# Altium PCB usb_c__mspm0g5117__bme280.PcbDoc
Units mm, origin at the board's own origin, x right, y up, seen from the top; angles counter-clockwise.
Board outline 82 x 52 mm, 2 copper layers (Top, Bottom), stack 0 mm thick; 27 components, 19 nets, 159 pads, 78 vias.
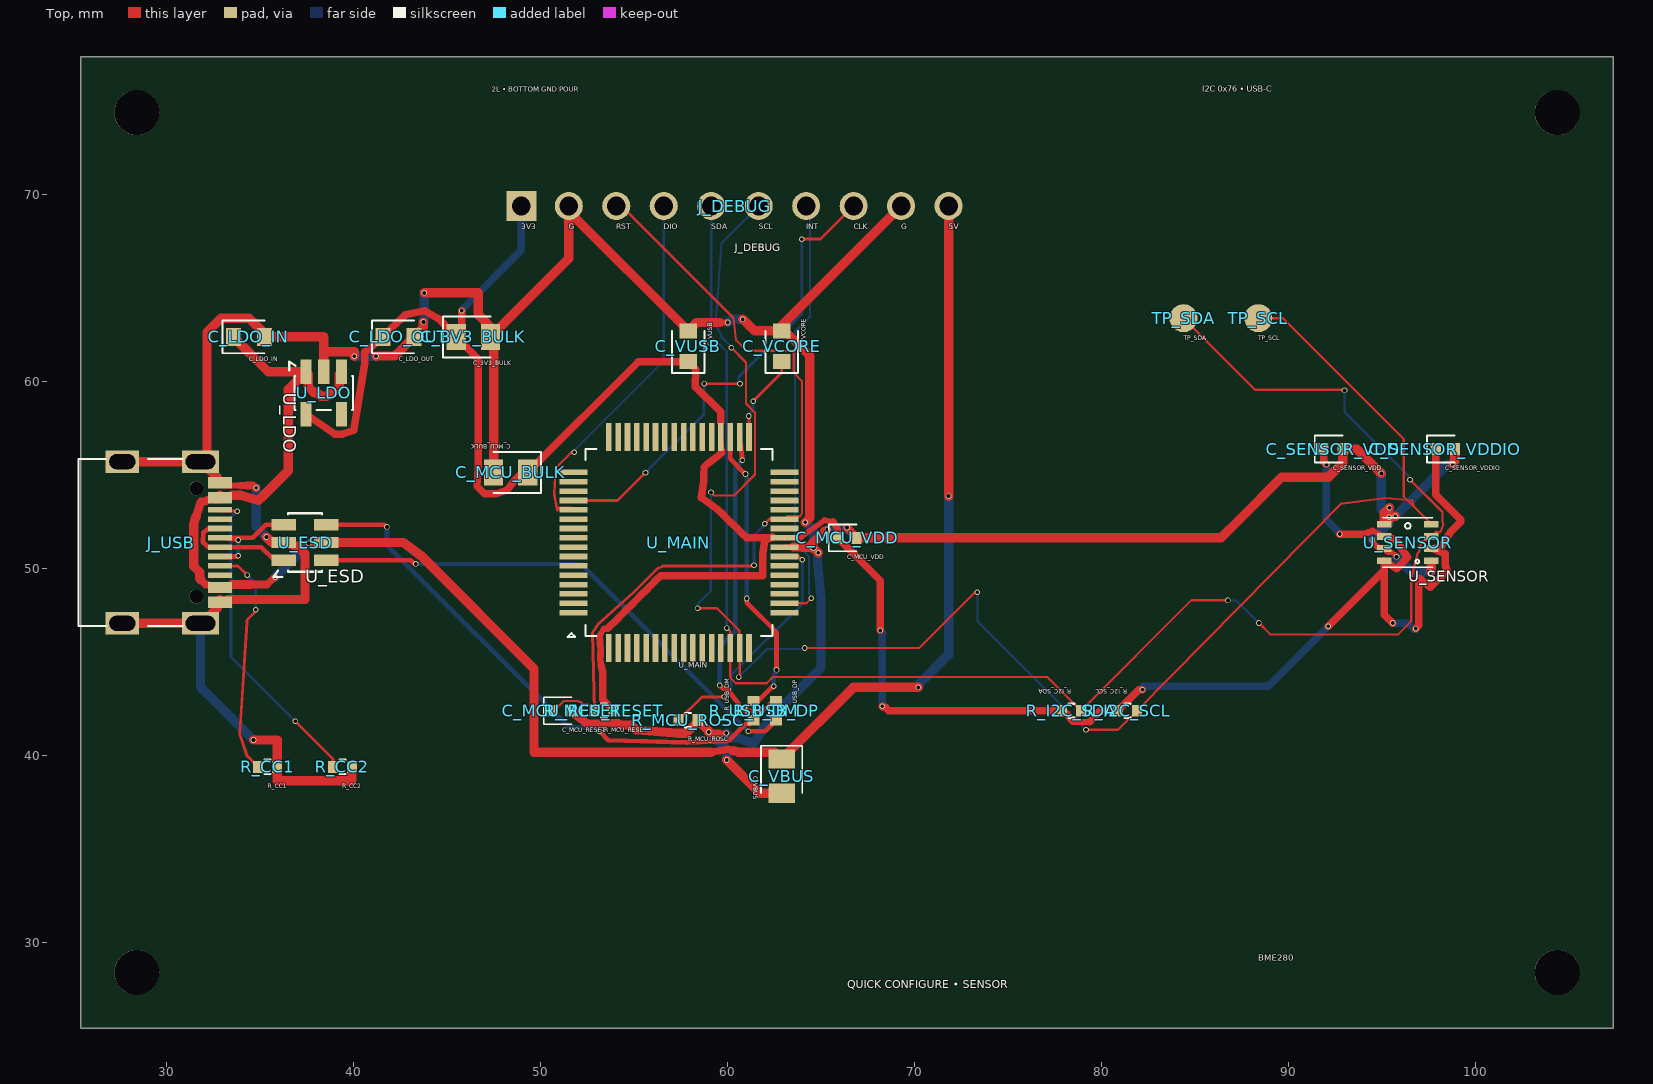
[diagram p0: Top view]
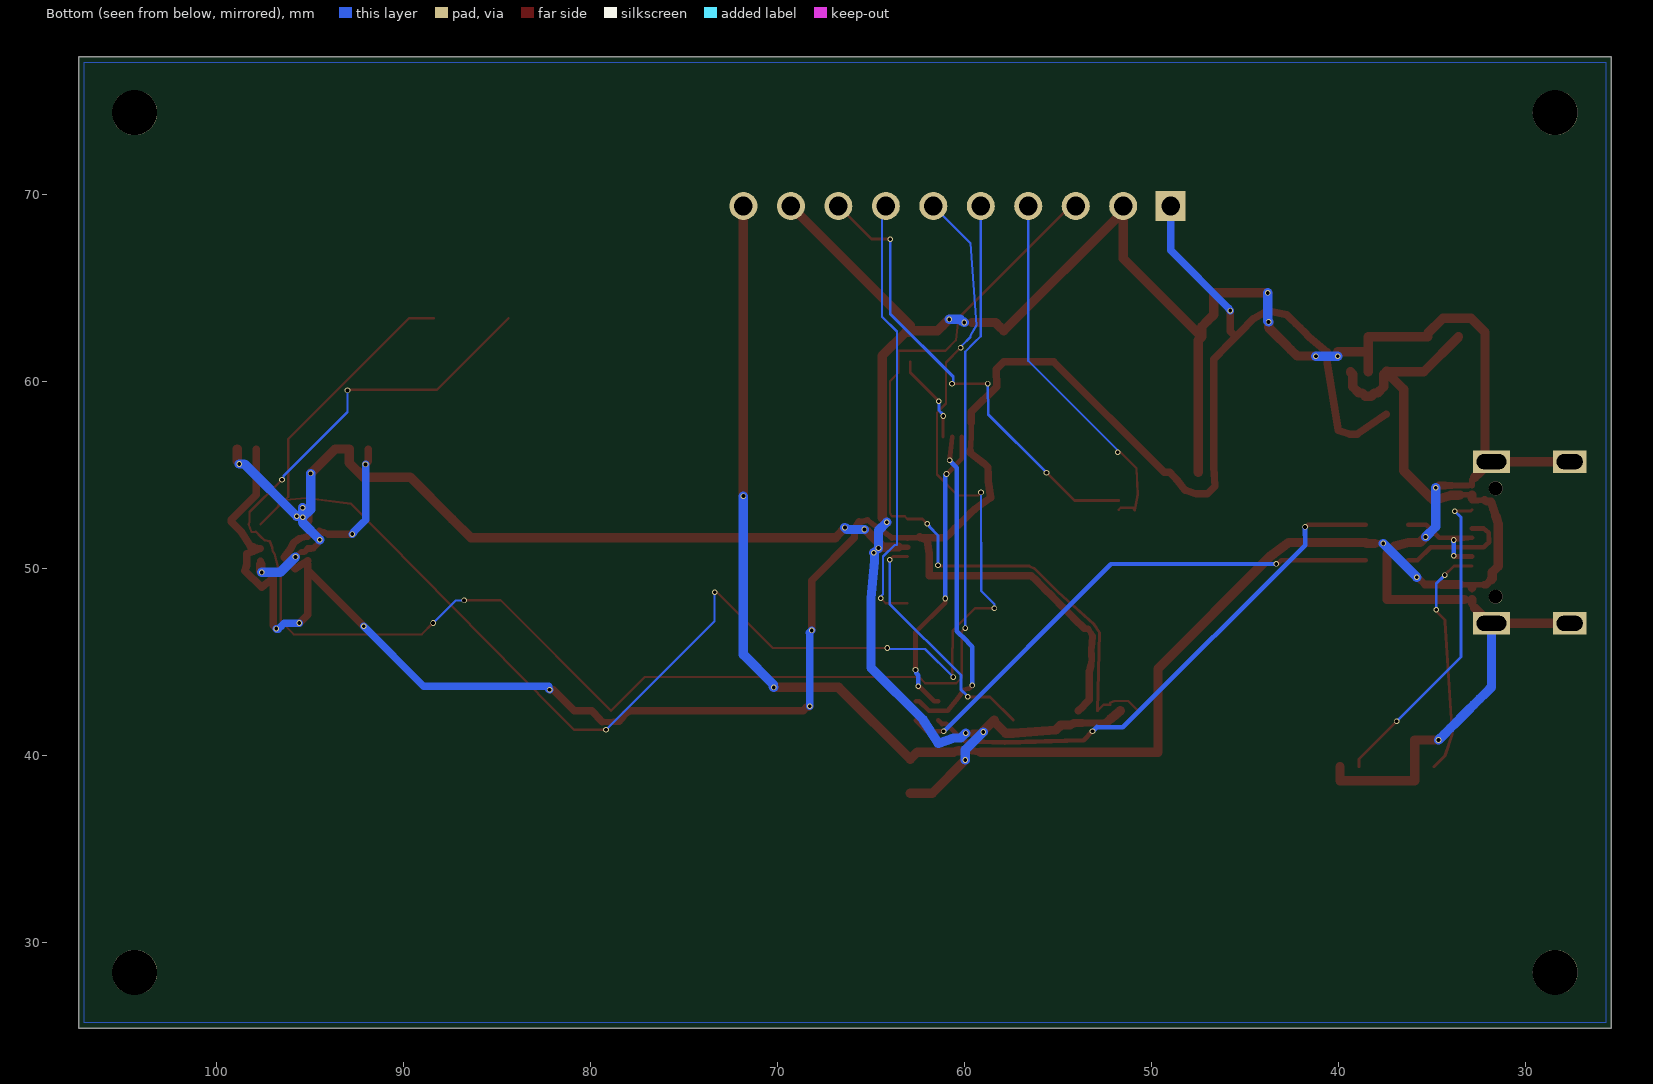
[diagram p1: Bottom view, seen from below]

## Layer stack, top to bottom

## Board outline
25.4,77.4 107.4,77.4 107.4,25.4 25.4,25.4

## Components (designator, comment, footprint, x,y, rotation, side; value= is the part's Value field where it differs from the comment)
C_3V3_BULK "" TSCIRCUIT-2.8500x1.4000mm 46.4,62.4 r0 top
C_LDO_IN "" TSCIRCUIT-2.4500x0.9500mm 34.4,62.4 r0 top
C_LDO_OUT "" TSCIRCUIT-2.4500x0.9500mm 42.4,62.4 r0 top
C_MCU_BULK "" TSCIRCUIT-2.8500x1.4000mm 48.4,55.15 r180 top
C_MCU_RESET "" TSCIRCUIT-1.5600x0.6400mm 51.15,42.4 r0 top
C_MCU_VDD "" TSCIRCUIT-1.5600x0.6400mm 66.4,51.65 r0 top
C_SENSOR_VDD "" TSCIRCUIT-1.5600x0.6400mm 92.4,56.4 r0 top
C_SENSOR_VDDIO "" TSCIRCUIT-1.5600x0.6400mm 98.4,56.4 r0 top
C_VBUS "" TSCIRCUIT-1.4000x2.8500mm 62.9,38.9 r270 top
C_VCORE "" TSCIRCUIT-0.9500x2.4500mm 62.9,61.9 r90 top
C_VUSB "" TSCIRCUIT-0.9500x2.4500mm 57.9,61.9 r90 top
J_DEBUG "" TSCIRCUIT-24.3600x1.5000mm 60.4,69.4 r0 top
J_USB "" TSCIRCUIT-6.7732x9.8502mm 30.113,51.4 r90 top
R_CC1 "" TSCIRCUIT-1.5600x0.6400mm 35.4,39.4 r0 top
R_CC2 "" TSCIRCUIT-1.5600x0.6400mm 39.4,39.4 r0 top
R_I2C_SCL "" TSCIRCUIT-1.5600x0.6400mm 81.4,42.4 r180 top
R_I2C_SDA "" TSCIRCUIT-1.5600x0.6400mm 78.4,42.4 r180 top
R_MCU_RESET "" TSCIRCUIT-1.5600x0.6400mm 53.4,42.4 r0 top
R_MCU_ROSC "" TSCIRCUIT-1.5600x0.6400mm 57.9,41.9 r0 top
R_USB_DM "" TSCIRCUIT-0.6400x1.5600mm 61.4,42.4 r90 top
R_USB_DP "" TSCIRCUIT-0.6400x1.5600mm 62.6,42.4 r90 top
TP_SCL "" TSCIRCUIT-1.5000x1.5000mm 88.4,63.4 r0 top
TP_SDA "" TSCIRCUIT-1.5000x1.5000mm 84.4,63.4 r0 top
U_ESD "" TSCIRCUIT-3.6000x2.5000mm 37.4,51.4 r0 top
U_LDO "" TSCIRCUIT-2.5000x3.6000mm 38.4,59.4 r270 top
U_MAIN "" TSCIRCUIT-12.8000x12.8000mm 57.4,51.4 r0 top
U_SENSOR "" TSCIRCUIT-3.2841x2.3142mm 96.4,51.4 r0 top

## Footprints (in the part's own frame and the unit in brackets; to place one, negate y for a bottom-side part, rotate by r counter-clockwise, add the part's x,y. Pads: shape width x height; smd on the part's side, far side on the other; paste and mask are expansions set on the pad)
TSCIRCUIT-0.6400x1.5600mm [mm]
  rect 0.54x0.64 smd: 1(-0.51,0) 2(0.51,0)
  silkscreen extent -0.15,-0.38 0.15,0.38
TSCIRCUIT-0.9500x2.4500mm [mm]
  rect 0.8x0.95 smd: 1(-0.825,0) 2(0.825,0)
  silkscreen extent -1.43,-0.87 0.82,0.88
TSCIRCUIT-1.4000x2.8500mm [mm]
  rect 1.025x1.4 smd: 1(-0.913,0) 2(0.913,0)
  silkscreen extent -1.62,-1.1 0.91,1.1
TSCIRCUIT-1.5000x1.5000mm [mm]
  round 1.5 smd: 1(0,0)
TSCIRCUIT-1.5600x0.6400mm [mm]
  rect 0.54x0.64 smd: 1(-0.51,0) 2(0.51,0)
  silkscreen extent -0.98,-0.72 0.51,0.72
TSCIRCUIT-2.4500x0.9500mm [mm]
  rect 0.8x0.95 smd: 1(-0.825,0) 2(0.825,0)
  silkscreen extent -1.43,-0.87 0.82,0.87
TSCIRCUIT-2.5000x3.6000mm [mm]
  rect 1.325x0.6 smd: 1(-1.137,-0.95) 2(-1.137,0) 3(-1.137,0.95) 4(1.138,0.95) 5(1.138,-0.95)
  silkscreen extent -1.69,-1.84 0.91,1.56
TSCIRCUIT-2.8500x1.4000mm [mm]
  rect 1.025x1.4 smd: 1(-0.913,0) 2(0.913,0)
  silkscreen extent -1.63,-1.1 0.91,1.1
TSCIRCUIT-3.2841x2.3142mm [mm]
  rect 0.767x0.364 smd: 1(1.259,-0.975) 2(1.259,-0.325) 3(1.259,0.325) 4(1.259,0.975) 5(-1.259,0.975) 6(-1.259,0.325) 7(-1.259,-0.325) 8(-1.259,-0.975)
  silkscreen extent -1.33,-1.33 1.33,1.33
TSCIRCUIT-3.6000x2.5000mm [mm]
  rect 1.325x0.6 smd: 1(-1.137,-0.95) 2(-1.137,0) 3(-1.137,0.95) 4(1.138,0.95) 5(1.138,0) 6(1.138,-0.95)
  silkscreen extent -1.69,-1.84 0.91,1.56
TSCIRCUIT-6.7732x9.8502mm [mm]
  rect 0.3x1.3 smd: 1(-3.35,-2.737) 2(-3.05,-2.737) 3(-2.55,-2.737) 4(-2.25,-2.737) 5(-1.75,-2.737) 6(-1.25,-2.737) 7(-0.75,-2.737) 8(-0.25,-2.737) 9(0.25,-2.737) 10(0.75,-2.737) 11(1.25,-2.737) 12(1.75,-2.737) 13(2.55,-2.737) 14(2.25,-2.737) 15(3.35,-2.737) 16(3.05,-2.737)
  rect 1.2x2 hole 0.8 slot 1.6 at 90 deg: 17(-4.325,-1.693) 18(4.325,-1.693)
  rect 1.2x1.8 hole 0.8 slot 1.4 at 90 deg: 19(4.325,2.487) 20(-4.325,2.487)
  round 0.75 hole 0.75 unplated: NPTH-1(-2.9,-1.468) NPTH-2(2.9,-1.468)
  silkscreen extent -4.47,-0.75 4.47,4.83
TSCIRCUIT-12.8000x12.8000mm [mm]
  rect 1.5x0.3 smd: 1(-5.65,-3.75) 2(-5.65,-3.25) 3(-5.65,-2.75) 4(-5.65,-2.25) 5(-5.65,-1.75) 6(-5.65,-1.25) 7(-5.65,-0.75) 8(-5.65,-0.25) 9(-5.65,0.25) 10(-5.65,0.75) 11(-5.65,1.25) 12(-5.65,1.75) 13(-5.65,2.25) 14(-5.65,2.75) 15(-5.65,3.25) 16(-5.65,3.75) 33(5.65,3.75) 34(5.65,3.25) 35(5.65,2.75) 36(5.65,2.25) 37(5.65,1.75) 38(5.65,1.25) 39(5.65,0.75) 40(5.65,0.25) 41(5.65,-0.25) 42(5.65,-0.75) 43(5.65,-1.25) 44(5.65,-1.75) 45(5.65,-2.25) 46(5.65,-2.75) 47(5.65,-3.25) 48(5.65,-3.75)
  rect 0.3x1.5 smd: 17(-3.75,5.65) 18(-3.25,5.65) 19(-2.75,5.65) 20(-2.25,5.65) 21(-1.75,5.65) 22(-1.25,5.65) 23(-0.75,5.65) 24(-0.25,5.65) 25(0.25,5.65) 26(0.75,5.65) 27(1.25,5.65) 28(1.75,5.65) 29(2.25,5.65) 30(2.75,5.65) 31(3.25,5.65) 32(3.75,5.65) 49(3.75,-5.65) 50(3.25,-5.65) 51(2.75,-5.65) 52(2.25,-5.65) 53(1.75,-5.65) 54(1.25,-5.65) 55(0.75,-5.65) 56(0.25,-5.65) 57(-0.25,-5.65) 58(-0.75,-5.65) 59(-1.25,-5.65) 60(-1.75,-5.65) 61(-2.25,-5.65) 62(-2.75,-5.65) 63(-3.25,-5.65) 64(-3.75,-5.65)
  silkscreen extent -5.95,-5.05 5,5
TSCIRCUIT-24.3600x1.5000mm [mm]
  rect 1.6x1.6 hole 1: 1(-11.43,0)
  round 1.5 hole 1: 2(-8.89,0) 3(-6.35,0) 4(-3.81,0) 5(-1.27,0) 6(1.27,0) 7(3.81,0) 8(6.35,0) 9(8.89,0) 10(11.43,0)

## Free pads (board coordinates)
  round 2.4 hole 2.4 unplated: NPTH-3(28.4,28.4) NPTH-4(104.4,28.4) NPTH-5(28.4,74.4) NPTH-6(104.4,74.4)

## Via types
v1: diameter 0.3, hole 0.2, Top to Bottom, 78 vias

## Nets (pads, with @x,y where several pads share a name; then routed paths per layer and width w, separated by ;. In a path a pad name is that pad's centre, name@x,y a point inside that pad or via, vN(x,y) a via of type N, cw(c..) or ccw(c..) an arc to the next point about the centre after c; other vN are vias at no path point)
".J_DEBUG > .pin4 to .U_MAIN > .pin12": J_DEBUG.4 U_MAIN.12 | length 19.8
  Top w0.12: U_MAIN.12 51.641,53.259 50.973,53.259 50.895,53.127 50.728,53.972 50.797,55.377 50.874,55.454 51.654,56.234 v1(51.8,56.234)
  Bottom w0.12: v1(51.8,56.234) 51.836,56.27 51.836,56.369 56.59,61.124 J_DEBUG.4
".J_DEBUG > .pin8 to .U_MAIN > .pin13": J_DEBUG.8 U_MAIN.13 | length 25.1
  Top w0.15: U_MAIN.13 54.123,53.65 v1(55.612,55.139) ; v1(58.759,59.903) 58.754,59.898 58.918,59.898 v1(60.667,59.898) ; v1(63.971,67.619) 63.983,67.631 64.981,67.631 J_DEBUG.8
  Bottom w0.15: v1(55.612,55.139) 55.64,55.167 58.735,58.262 v1(58.759,59.903) ; v1(60.667,59.898) 60.604,59.961 60.604,60.265 63.971,63.632 v1(63.971,67.619)
".U_MAIN > .pin42 to .R_MCU_ROSC > .pin1": R_MCU_ROSC.1 U_MAIN.42 | length 13
  Top w0.15: R_MCU_ROSC.1 58.63,43.14 v1(59.82,43.142) ; U_MAIN.42 63.825,50.65 63.984,50.491 v1(64.004,50.471)
  Bottom w0.15: v1(59.82,43.142) 59.844,43.166 59.844,43.182 60.188,43.526 60.188,44.303 64.004,48.119 v1(64.004,50.471)
GND: C_3V3_BULK.2 C_LDO_IN.2 C_LDO_OUT.2 C_MCU_BULK.2 C_MCU_RESET.2 C_MCU_VDD.2 C_SENSOR_VDD.2 C_SENSOR_VDDIO.2 C_VBUS.2 C_VCORE.2 C_VUSB.2 J_DEBUG.2 J_DEBUG.9 J_USB.1 J_USB.2 J_USB.15 J_USB.16 J_USB.17 J_USB.18 J_USB.19 J_USB.20 R_CC1.2 R_CC2.2 R_MCU_ROSC.2 U_ESD.2 U_LDO.2 U_MAIN.41 U_SENSOR.1 U_SENSOR.5 U_SENSOR.7 | length 209.8
  Top w0.25: U_SENSOR.7@95.462,50.9 95.713,50.775 v1(95.789,50.628)
  Top w0.275: J_USB.2 J_USB.2@33.271,48.35
  Top w0.3: J_USB.1@32.699,47.9 J_USB.1 J_USB.2@32.849,48.2 ; 32.699,54.9 J_USB.15 J_USB.16@32.849,54.6 ; J_USB.16 32.945,54.461 33.037,54.45 J_USB.16@33.318,54.45 ; U_MAIN.41@63.526,51.15 U_MAIN.41 ; U_MAIN.41@63.55,51.15 U_MAIN.41 ; U_MAIN.41@63.8,51.15 63.706,51.15 63.612,51.15 63.519,51.15 63.425,51.15 63.331,51.15 63.238,51.15 63.144,51.15 U_MAIN.41
  Top w0.31: J_USB.16 J_USB.15@32.849,54.6
  Top w0.312: J_USB.16@33.318,54.45 33.599,54.45 ; v1(94.491,51.553) 94.525,51.4 U_SENSOR.7@94.837,51.088
  Top w0.325: 33.599,54.45 33.941,54.45 ; 59.535,41.192 v1(59.939,41.205) ; 59.596,63.169 v1(60.013,63.169) ; U_SENSOR.7@94.837,51.088 U_SENSOR.7@94.969,51.075 ; U_SENSOR.7 95.335,50.881 U_SENSOR.7@95.462,50.9
  Top w0.35: 33.941,54.45 34.283,54.45 ; 65.199,51.996 65.237,51.996 v1(65.354,52.095)
  Top w0.364: U_SENSOR.7@94.969,51.075 U_SENSOR.7 ; U_SENSOR.5@95.141,52.557 U_SENSOR.5 ; U_SENSOR.1@97.659,50.243 U_SENSOR.1 ; U_SENSOR.5 95.323,52.557 U_SENSOR.5
  Top w0.375: 52.431,41.744 52.853,41.744 53.275,41.744
  Top w0.4: 53.275,41.744 53.697,41.744
  Top w0.425: 34.283,54.45 34.625,54.45 34.784,54.329 v1(34.786,54.327) ; 58.89,41.42 59.13,41.18 59.535,41.192
  Top w0.45: 52.174,41.962 52.431,41.744 ; 53.697,41.744 54.119,41.744 54.36,41.639 ; v1(66.4,52.2) 66.655,51.925 C_MCU_VDD.2
  Top w0.475: U_MAIN.41@63.526,51.15 64.003,51.15 ; U_MAIN.41@63.55,51.15 64.05,51.15 ; U_MAIN.41@63.8,51.15 64.076,51.15
  Top w0.5: J_USB.20 J_USB.17 31.874,47.075 32.474,47.675 J_USB.1@32.699,47.9 ; J_USB.19 J_USB.18 ; 32.699,54.9 32.474,55.125 31.874,55.725 J_USB.18 ; J_USB.1@32.849,48.2 J_USB.2 ; J_USB.2@33.271,48.35 33.693,48.35 37.4,48.35 37.4,50.8 37,51.2 U_ESD.2 35.63,51.4 v1(35.333,51.697) ; v1(34.641,40.833) 35.91,40.833 R_CC1.2 35.91,38.65 39.91,38.65 R_CC2.2 ; v1(40.032,61.365) 40.032,61.6 38.4,61.6 U_LDO.2 38.4,62.4 C_LDO_IN.2 35.225,62.575 34.4,63.4 32.9,63.4 32.154,62.654 32.154,56.073 J_USB.18 ; v1(41.2,61.367) 41.209,61.376 41.399,61.376 41.8,61.376 42.201,61.376 42.542,61.717 42.884,62.059 C_LDO_OUT.2 43.732,62.907 v1(43.732,63.2) ; v1(43.779,64.753) 46.657,64.753 46.657,63.598 46.985,63.271 47.313,62.943 47.313,62.671 C_3V3_BULK.2 ; C_MCU_BULK.2 47.487,62.225 C_3V3_BULK.2 ; C_MCU_RESET.2 51.917,42.181 52.174,41.962 ; 54.36,41.639 54.845,41.639 55.113,41.37 57.4,41.2 57.8,41.2 58.41,41.81 R_MCU_ROSC.2 ; 58.89,41.42 58.65,41.66 R_MCU_ROSC.2 ; v1(59,41.261) 59,41.31 R_MCU_ROSC.2 ; 59.596,63.169 59.178,63.169 58.761,63.169 58.344,63.169 58.122,62.947 C_VUSB.2 51.51,69.115 J_DEBUG.2 51.51,66.597 C_3V3_BULK.2 ; v1(59.956,39.762) 61.731,37.988 C_VBUS.2 ; v1(60.816,63.335) 60.867,63.284 60.882,63.284 61.162,63.005 61.441,62.725 61.927,62.725 62.414,62.725 C_VCORE.2 ; 64.003,51.15 64.479,51.15 64.529,51.1 v1(64.6,51.1) ; 64.05,51.15 v1@64.549,51.15 ; 64.076,51.15 64.353,51.15 64.635,51.432 64.917,51.714 65.199,51.996 ; v1(64.162,52.485) 64.4,52.723 64.4,60.9 64.4,61.4 63.15,62.65 62.975,62.65 C_VCORE.2 ; v1@64.55,51.15 v1(64.85,50.85) ; C_MCU_VDD.2 67.404,51.65 67.899,51.65 68.393,51.65 68.887,51.65 69.382,51.65 69.876,51.65 70.37,51.65 70.865,51.65 71.359,51.65 71.853,51.65 72.348,51.65 72.842,51.65 73.336,51.65 73.831,51.65 74.325,51.65 74.819,51.65 75.314,51.65 75.808,51.65 76.302,51.65 76.797,51.65 77.291,51.65 77.785,51.65 78.28,51.65 86.4,51.65 87.4,52.65 89.65,54.9 92.15,54.9 92.91,55.66 C_SENSOR_VDD.2 93.666,56.4 94.899,55.167 94.912,55.167 v1(94.983,55.096) ; J_DEBUG.9 62.9,63.01 C_VCORE.2 ; 95.141,52.557 95.141,52.992 v1(95.414,53.265) ; v1(95.4,52.75) 95.4,52.634 95.323,52.557 95.566,52.8 v1(95.725,52.8) ; v1(97.6,49.8) 97.659,49.859 U_SENSOR.1@97.659,50.243 ; v1(98.8,55.6) 98.834,55.634 98.834,55.681 98.91,55.757 C_SENSOR_VDDIO.2
  Bottom w0.5: J_USB.17 31.806,46.588 31.806,46.1 31.806,45.613 31.806,45.126 31.806,44.639 31.806,44.151 31.806,43.664 32.121,43.349 32.436,43.035 32.751,42.72 33.066,42.406 33.381,42.091 33.696,41.777 34.011,41.462 34.326,41.148 v1(34.641,40.833) ; v1(34.786,54.327) 34.786,52.244 v1(35.333,51.697) ; v1(40.032,61.365) 40.038,61.359 40.204,61.359 40.213,61.367 40.706,61.367 v1(41.2,61.367) ; v1(43.732,63.2) 43.779,63.247 v1(43.779,64.753) ; v1(59,41.261) 59.956,40.305 v1(59.956,39.762) ; v1(59.939,41.205) 60.205,40.938 60.568,40.938 61.4,40.65 62.214,41.914 65,44.701 65,48.4 64.816,50.391 64.816,50.884 v1(64.85,50.85) ; v1(60.013,63.169) 60.066,63.222 60.114,63.222 60.227,63.335 60.522,63.335 v1(60.816,63.335) ; v1(64.162,52.485) 64.6,52.047 v1(64.6,51.1) ; v1(65.354,52.095) 66.295,52.095 v1(66.4,52.2) ; v1(94.491,51.553) 95.414,52.476 v1(95.414,53.265) ; v1(94.983,55.096) 94.983,53.167 v1(95.4,52.75) ; v1(95.725,52.8) 98.525,55.6 v1(98.8,55.6) ; v1(95.789,50.628) 96.617,49.8 v1(97.6,49.8)
MAIN_RESET: C_MCU_RESET.1 J_DEBUG.3 R_MCU_RESET.1 U_MAIN.38 | length 43.8
  Top w0.12: C_MCU_RESET.1 50.822,42.506 51.222,42.906 51.598,42.915 51.998,42.906 52.213,42.826 52.209,42.722 52.568,42.722 R_MCU_RESET.1 ; J_DEBUG.3 54.332,69.4 60.32,63.412 60.462,62.221 61.019,61.664 63.468,61.664 63.55,61.664 63.55,60.481 63.984,60.032 63.984,53.433 63.984,53.326 63.989,53.003 63.93,52.85 63.866,52.799 63.199,52.799 U_MAIN.38
  Top w0.15: R_MCU_RESET.1 52.777,46.592 53.087,47.042 54.995,48.753 56.04,49.795 56.251,50.002 56.53,50.139 61.28,50.139 61.374,50.139 v1(61.418,50.183) ; v1(62,52.4) 62.25,52.65 U_MAIN.38
  Bottom w0.15: v1(61.418,50.183) 61.418,51.778 61.88,52.24 61.88,52.28 v1(62,52.4)
MSP_VCORE: C_VCORE.1 U_MAIN.32 | length 4.8
  Top w0.15: v1(61.143,58.169) 61.143,57.057 U_MAIN.32 ; v1(61.373,58.961) 61.407,58.995 62.9,60.488 C_VCORE.1
  Bottom w0.15: v1(61.143,58.169) 61.19,58.216 61.19,58.288 61.373,58.471 v1(61.373,58.961)
SENSOR_INT: J_DEBUG.7 U_MAIN.47 | length 23.4
  Top w0.12: U_MAIN.47 64.215,48.15 v1(64.482,48.417)
  Bottom w0.12: J_DEBUG.7 64.413,69.197 64.413,63.484 63.612,62.683 63.612,51.27 63.739,51.27 64.356,50.653 64.356,48.632 64.516,48.471 64.516,48.451 v1(64.482,48.417)
SENSOR_SCL: J_DEBUG.6 R_I2C_SCL.1 TP_SCL.1 U_MAIN.50 U_SENSOR.4 | length 94.9
  Top w0.12: v1(58.402,47.883) 59.435,47.883 60.626,46.692 60.626,45.774 U_MAIN.50 60.65,44.321 60.6,44.271 v1(60.6,44.2) ; v1(59.121,54.079) 59.136,54.024 59.161,54.024 59.277,53.908 60.35,53.908 61.476,55.035 61.476,58.347 60.992,58.831 60.992,58.894 60.992,61.036 v1(60.21,61.818) ; v1(64.133,45.754) 70.259,45.754 73.233,48.728 73.359,48.728 v1(73.369,48.738) ; v1(79.178,41.386) 80.896,41.386 R_I2C_SCL.1 92.827,53.476 95.205,53.786 96.629,53.644 96.713,53.321 U_SENSOR.4 96.185,53.849 96.185,56.937 89.721,63.4 TP_SCL.1
  Bottom w0.12: v1(58.402,47.883) 58.402,48.104 59.099,48.801 v1(59.121,54.079) ; v1(60.21,61.818) 60.147,61.881 60.147,61.921 59.676,62.392 59.676,62.476 59.357,63.03 59.676,67.406 J_DEBUG.6 ; v1(60.6,44.2) 62.108,45.708 63.974,45.708 64.087,45.708 v1(64.133,45.754) ; v1(73.369,48.738) 73.369,47.195 79.167,41.397 v1(79.178,41.386)
SENSOR_SDA: J_DEBUG.5 R_I2C_SDA.1 TP_SDA.1 U_MAIN.51 U_SENSOR.3 | length 92.1
  Top w0.12: v1(59.965,46.82) 60.069,46.716 60.15,46.635 U_MAIN.51 60.15,44.17 60.447,43.873 62.096,43.873 62.43,44.207 77.103,44.207 R_I2C_SDA.1 84.818,48.308 86.713,48.308 86.767,48.308 v1(86.773,48.302) ; TP_SDA.1 88.227,59.573 92.815,59.573 92.971,59.573 v1(93.008,59.536) ; v1(88.432,47.091) 89.038,46.485 95.886,46.485 96.582,47.182 96.582,49.511 96.916,50.809 97.026,50.964 97.039,51.125 97.167,51.467 97.419,51.522 97.455,51.522 U_SENSOR.3 97.907,51.974 97.912,51.979 98.143,51.958 98.299,52.389 98.248,52.487 98.248,53.028 v1(96.514,54.762)
  Bottom w0.12: J_DEBUG.5 59.13,62.439 59.46,62.11 59.965,61.604 v1(59.965,46.82) ; v1(86.773,48.302) 87.212,48.302 88.315,47.199 88.324,47.199 v1(88.432,47.091) ; v1(93.008,59.536) 93.008,58.376 96.43,54.954 96.43,54.846 v1(96.514,54.762)
usb-dm-mcu: R_USB_DM.2 U_MAIN.30 | length 15.8
  Top w0.25: U_MAIN.30 60.15,55.874 v1(60.961,55.063) ; v1(61.024,48.403) 61.039,48.388 61.039,48.176 62.622,46.594 v1(62.622,44.584) ; R_USB_DM.2 61.62,42.91 62.348,43.639 62.418,43.639 v1(62.482,43.703)
  Bottom w0.25: v1(60.961,55.063) 61.024,55 61.024,54.902 v1(61.024,48.403) ; v1(62.482,43.703) 62.482,44.304 62.587,44.409 62.587,44.549 v1(62.622,44.584)
usb-dm-phy: R_USB_DM.1 U_ESD.4 | length 28.7
  Top w0.25: U_ESD.4 41.622,52.35 41.739,52.233 v1(41.78,52.233) ; v1(53.154,41.301) 53.619,40.827 57.843,40.701 59.956,40.761 60.125,40.837 60.974,41.705 61.204,41.694 R_USB_DM.1
  Bottom w0.25: v1(41.78,52.233) 41.764,51.265 51.533,41.523 52.93,41.525 53.149,41.306 v1(53.154,41.301)
usb-dm-port: J_USB.7 J_USB.9 U_ESD.3 | length 6.5
  Top w0.25: J_USB.7 33.099,50.65 33.349,50.65 33.599,50.65 33.784,50.65 v1(33.823,50.689) ; v1(33.827,51.533) J_USB.9 34.609,51.65 35.309,52.35 U_ESD.3
  Bottom w0.25: v1(33.823,50.689) 33.823,50.929 33.823,51.169 33.823,51.41 33.843,51.43 33.843,51.483 v1(33.827,51.533)
usb-dp-mcu: R_USB_DP.2 U_MAIN.31 | length 17.7
  Top w0.25: v1(59.58,43.753) 59.67,43.663 59.759,43.574 59.859,43.574 60.025,43.525 60.349,43.084 60.9,42.4 61.9,42.4 62.42,42.91 R_USB_DP.2 ; U_MAIN.31 v1(60.8,55.8)
  Bottom w0.25: v1(59.58,43.753) 59.58,43.984 59.58,44.214 59.58,44.445 59.58,44.675 59.58,44.906 59.58,45.136 59.58,45.367 59.58,45.597 59.58,45.828 59.746,45.994 59.912,46.159 60.078,46.325 60.243,46.491 60.409,46.657 60.409,46.907 60.409,47.156 60.409,47.406 60.409,47.656 60.409,47.906 60.409,48.155 60.409,48.405 60.409,48.655 60.409,48.905 60.409,49.154 60.409,49.404 60.409,49.654 60.409,49.904 60.409,50.153 60.409,50.403 60.409,50.653 60.409,50.902 60.409,51.152 60.409,51.402 60.409,51.652 60.409,51.901 60.409,52.151 60.409,52.401 60.409,52.651 60.409,52.9 60.409,53.15 60.409,53.4 60.409,53.65 60.409,53.899 60.409,54.149 60.409,54.399 60.409,54.648 60.409,54.898 60.409,55.148 60.409,55.398 60.545,55.533 60.681,55.669 60.681,55.681 v1(60.8,55.8)
usb-dp-phy: R_USB_DP.1 U_ESD.6 | length 28.1
  Top w0.25: U_ESD.6 43.047,50.45 43.217,50.28 43.275,50.28 v1(43.328,50.255) ; v1(61.119,41.296) 62.019,41.309 R_USB_DP.1
  Bottom w0.25: v1(43.328,50.255) 52.174,50.241 61.095,41.315 v1(61.119,41.296)
usb-dp-port: J_USB.8 J_USB.10 U_ESD.1 | length 6.2
  Top w0.25: J_USB.10 32.644,52.15 32.44,52.15 32.235,52.15 31.955,51.916 31.938,51.423 32.076,51.285 32.214,51.147 32.425,51.147 32.635,51.147 32.846,51.147 J_USB.8 35.065,51.135 35.764,50.451 U_ESD.1@36.262,50.451
USB_CC1: J_USB.6 R_CC1.1 | length 12.6
  Top w0.15: J_USB.6 33.811,50.15 v1(34.305,49.656) ; v1(34.762,47.804) 34.756,47.798 34.756,47.716 34.299,47.259 34.299,47.155 33.906,41.148 34.296,39.991 R_CC1.1
  Bottom w0.15: v1(34.305,49.656) 34.336,49.625 34.762,49.199 v1(34.762,47.804)
USB_CC2: J_USB.12 R_CC2.1 | length 17
  Top w0.15: J_USB.12 32.92,53.079 v1(33.779,53.079) ; v1(36.883,41.831) 36.892,41.822 38.89,39.824 R_CC2.1
  Bottom w0.15: v1(33.779,53.079) 33.757,53.057 33.753,53.057 33.445,52.749 33.445,52.689 33.445,45.269 v1(36.883,41.831)
VBUS5: C_LDO_IN.1 C_VBUS.1 J_DEBUG.10 J_USB.3 J_USB.4 J_USB.13 J_USB.14 U_ESD.5 U_LDO.1 U_LDO.3 | length 99.4
  Top w0.275: J_USB.3 J_USB.4@32.849,49
  Top w0.3: 32.181,53.666 32.536,53.65 J_USB.14 32.849,53.8 ; J_USB.4@32.199,49.15 J_USB.4 ; J_USB.3@32.849,49 J_USB.4 ; J_USB.13 32.943,53.95 33.037,53.95 33.13,53.95 33.224,53.95 33.318,53.95 33.412,53.95 33.499,53.95 ; 33.499,49.15 33.412,49.15 33.318,49.15 33.224,49.15 33.13,49.15 33.037,49.15 32.943,49.15 J_USB.4
  Top w0.35: v1(37.6,51.35) U_ESD.5@38.044,51.35
  Top w0.375: 35.37,49.15 35.709,49.489 35.75,49.489 v1(35.8,49.539)
  Top w0.4: 31.838,49.4 32.087,49.15 J_USB.4@32.199,49.15 ; 59.134,40.187 59.58,40.262 60.025,40.338 60.307,40.262
  Top w0.425: 34.485,49.15 34.927,49.15 35.37,49.15
  Top w0.437: 31.706,53.194 31.838,53.588 32.056,53.588 32.181,53.666
  Top w0.45: 31.575,52.8 31.706,53.194
  Top w0.475: J_USB.13@32.849,53.8 J_USB.13 ; 33.499,49.15 33.505,49.15 33.599,49.15 ; 33.499,53.95 33.505,53.95 33.599,53.932
  Top w0.5: 31.575,52.8 31.444,52.406 31.444,50.125 31.761,49.807 31.761,49.476 31.838,49.4 ; C_LDO_IN.1 35.438,60.537 U_LDO.1 ; 33.599,49.15 34.042,49.15 34.485,49.15 ; 33.599,53.932 33.988,53.922 34.9,53.65 35.155,53.893 36.51,55.248 36.51,59.597 U_LDO.1 ; U_ESD.5@38.044,51.35 38.487,51.35 U_ESD.5 38.993,51.4 39.449,51.401 39.905,51.401 40.361,51.401 40.817,51.402 41.273,51.402 41.729,51.403 42.185,51.403 42.641,51.403 43.65,50.65 49.65,44.65 49.65,43.65 49.65,40.185 55.738,40.185 56.223,40.185 56.708,40.186 57.194,40.186 57.679,40.186 58.164,40.186 58.649,40.186 59.134,40.187 ; U_LDO.3 39.35,60.517 39.233,60.4 39.233,59.733 38.9,59.4 38.733,59.4 38.567,59.233 38.233,59.233 38.067,59.4 37.9,59.4 37.567,59.733 37.567,60.4 37.4,60.567 37.421,60.567 U_LDO.1 ; 60.307,40.262 60.59,40.187 62.525,40.187 C_VBUS.1 66.737,43.649 v1(70.2,43.649) ; v1(71.83,53.884) 71.83,53.9 J_DEBUG.10
  Bottom w0.5: v1(35.8,49.539) 35.8,49.55 v1(37.6,51.35) ; v1(70.2,43.649) 70.228,43.677 70.228,43.8 71.83,45.402 v1(71.83,53.884)
VCC_3V3: C_3V3_BULK.1 C_LDO_OUT.1 C_MCU_BULK.1 C_MCU_VDD.1 C_SENSOR_VDD.1 C_SENSOR_VDDIO.1 C_VUSB.1 J_DEBUG.1 R_I2C_SCL.2 R_I2C_SDA.2 R_MCU_RESET.2 U_LDO.5 U_MAIN.29 U_MAIN.40 U_SENSOR.2 U_SENSOR.6 U_SENSOR.8 | length 149.9
  Top w0.275: 64.404,52.03 64.669,52.22 64.935,52.41 65.2,52.6
  Top w0.3: 53.25,46.575 53.35,46.75 53.4,46.775 ; 59.65,57.8 59.65,57.75 59.65,57.65 59.65,57.55 59.65,57.45 59.65,57.35 59.65,57.25 59.65,57.15 U_MAIN.29 U_MAIN.29@59.694,56.3 ; U_MAIN.40@62.375,51.65 62.712,51.65 U_MAIN.40 ; 94.525,52.025 94.833,51.875 U_SENSOR.6
  Top w0.301: U_MAIN.40@62.374,51.65 62.712,51.65 U_MAIN.40
  Top w0.312: 53.15,46.4 53.25,46.575 ; U_MAIN.40 63.059,51.659 63.33,51.656 63.602,51.652 63.873,51.649 64.139,51.839 64.404,52.03
  Top w0.325: 65.2,52.6 65.53,52.503 ; 78.775,41.8 79.075,41.8 79.375,41.8
  Top w0.337: 65.53,52.503 65.65,52.525
  Top w0.35: 78.31,42.02 78.475,41.8 78.775,41.8 ; 94.282,51.938 94.525,52.025
  Top w0.363: 53.15,46.4 53.183,46.022 53.217,45.644 53.202,45.372 53.188,45.1 53.252,44.805 ; 94.038,51.852 94.282,51.938
  Top w0.364: U_SENSOR.6 95.171,51.725 95.6,51.6 ; 98.042,50.933 U_SENSOR.2 98.042,51.164 ; U_SENSOR.8@95.141,50.243 U_SENSOR.8 U_SENSOR.8@95.141,50.243
  Top w0.375: 53.4,46.775 53.55,46.8 53.595,46.806 ; 65.65,52.525 65.771,52.321 65.893,52.117 65.891,51.883 C_MCU_VDD.1
  Top w0.387: R_I2C_SDA.2@78.145,42.24 78.31,42.02
  Top w0.4: U_LDO.5 39,57.2 39.4,57.2 40,57.4 40.6,61 40.6,61.6 C_LDO_OUT.1 41.81,62.639 42.045,62.877 42.281,63.116 42.516,63.354 42.751,63.593 43.8,63.8 44.547,63.363 44.782,63.123 45.017,62.882 45.252,62.641 C_3V3_BULK.1 ; v1(45.783,63.807) 45.783,62.695 C_3V3_BULK.1 ; 53.252,44.805 53.317,44.509 53.317,44.13 53.317,43.751 53.317,43.372 53.317,42.993 53.515,42.795 53.712,42.598 R_MCU_RESET.2 ; 53.595,46.806 54.098,47.3 54.356,47.559 54.615,47.818 54.874,48.077 55.132,48.335 55.391,48.594 55.65,48.853 55.909,49.112 56.167,49.37 56.426,49.629 56.817,49.629 57.208,49.629 57.598,49.629 57.989,49.629 58.38,49.629 58.771,49.629 59.162,49.629 59.552,49.629 59.943,49.629 60.334,49.629 60.725,49.629 61.115,49.629 61.506,49.629 61.897,49.629 61.897,50.015 61.897,50.401 61.897,50.786 62,51.5 62.4,51.7 U_MAIN.40@62.375,51.65 ; 59.65,57.8 59.65,57.85 59.647,58.391 58.28,59.72 58.302,60.673 C_VUSB.1 55.238,61.075 C_MCU_BULK.1 49.033,55.15 48.818,54.931 48.603,54.713 48.2,54.2 47.6,54 47,54 46.6,54.4 46.673,55.444 46.673,55.829 46.673,56.214 46.673,56.598 46.673,56.983 46.673,57.368 46.673,57.753 46.673,58.137 46.673,58.522 46.673,58.907 46.673,59.292 46.673,59.676 46.673,60.061 46.673,60.446 46.673,60.831 46.673,61.215 46.436,61.452 46.199,61.689 45.962,61.926 45.725,62.163 C_3V3_BULK.1 ; 59.694,56.3 59.7,56.2 58.957,55.634 58.744,55.42 58.739,55.043 58.734,54.666 58.6,53.8 59.49,53.158 59.745,52.906 60.001,52.655 60.256,52.403 60.511,52.152 60.767,51.901 61.022,51.649 61.36,51.649 61.698,51.649 62.036,51.65 U_MAIN.40@62.374,51.65 ; C_MCU_VDD.1 68.172,49.368 v1(68.172,46.697) ; v1(68.276,42.638) 68.339,42.575 68.462,42.575 68.637,42.4 R_I2C_SDA.2 R_I2C_SDA.2@78.145,42.24 ; 79.375,41.8 79.562,42.002 79.749,42.204 79.945,42.4 80.26,42.4 80.575,42.4 R_I2C_SCL.2 82.01,43.52 v1(82.2,43.52) ; C_SENSOR_VDD.1 91.89,56.071 91.89,55.742 91.955,55.677 91.955,55.667 v1(92.044,55.578) ; v1(92.144,46.921) 92.146,46.923 95.141,49.918 95.141,50.243 95.141,50.064 95.141,49.704 95.141,49.343 95.141,48.982 95.141,48.622 95.141,48.261 95.141,47.9 95.141,47.54 95.359,47.322 95.576,47.105 v1(95.59,47.091) ; v1(92.75,51.852) 93.072,51.852 93.394,51.852 93.716,51.852 94.038,51.852 ; U_SENSOR.8 95.339,50.3 95.538,50.175 95.8,50 96.4,50.6 96.063,51.05 95.887,51.4 95.6,51.6 ; v1(96.82,46.795) 96.99,46.965 96.99,47.327 96.99,47.689 96.99,48.051 96.99,48.413 96.99,48.775 96.99,49.137 96.99,49.499 97.6,49 98.5,49.9 98.4,50.2 98.4,50.8 98.042,50.933 ; C_SENSOR_VDDIO.1 97.89,56.05 97.89,55.7 97.89,55.349 97.89,54.999 97.89,54.649 97.89,54.299 97.89,53.948 98.156,53.682 98.423,53.415 98.689,53.149 98.956,52.882 99.222,52.616 99.222,52.516 98.953,52.247 98.684,51.978 98.2,51.2 98.042,51.164
  Bottom w0.4: v1(45.783,63.807) 45.876,63.9 45.876,63.932 48.97,67.025 J_DEBUG.1 ; v1(68.172,46.697) 68.299,46.57 68.276,46.548 v1(68.276,42.638) ; v1(82.2,43.52) 82.232,43.552 82.232,43.698 88.921,43.698 v1(92.144,46.921) ; v1(92.044,55.578) 92.044,55.206 92.044,54.835 92.044,54.463 92.044,54.092 92.044,53.72 92.044,53.348 92.044,52.977 92.044,52.605 92.254,52.395 92.464,52.185 92.673,51.976 92.673,51.929 v1(92.75,51.852) ; v1(95.59,47.091) 95.989,47.091 96.388,47.091 96.547,46.932 96.707,46.772 96.797,46.772 v1(96.82,46.795)
pads on no net: J_USB.5 J_USB.11 J_USB.NPTH-1 J_USB.NPTH-2 U_LDO.4 U_MAIN.1 U_MAIN.2 U_MAIN.3 U_MAIN.4 U_MAIN.5 U_MAIN.6 U_MAIN.7 U_MAIN.8 U_MAIN.9 U_MAIN.10 U_MAIN.11 U_MAIN.14 U_MAIN.15 U_MAIN.16 U_MAIN.17 U_MAIN.18 U_MAIN.19 U_MAIN.20 U_MAIN.21 U_MAIN.22 U_MAIN.23 U_MAIN.24 U_MAIN.25 U_MAIN.26 U_MAIN.27 U_MAIN.28 U_MAIN.33 U_MAIN.34 U_MAIN.35 U_MAIN.36 U_MAIN.37 U_MAIN.39 U_MAIN.43 U_MAIN.44 U_MAIN.45 U_MAIN.46 U_MAIN.48 U_MAIN.49 U_MAIN.52 U_MAIN.53 U_MAIN.54 U_MAIN.55 U_MAIN.56 U_MAIN.57 U_MAIN.58 U_MAIN.59 U_MAIN.60 U_MAIN.61 U_MAIN.62 U_MAIN.63 U_MAIN.64

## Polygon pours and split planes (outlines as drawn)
GND on Bottom (solid): 107.1,77.1 25.7,77.1 25.7,25.7 107.1,25.7

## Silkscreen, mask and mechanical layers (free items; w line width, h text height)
Top Overlay:
  text "2L • BOTTOM GND POUR" at 47.4,75.4 h0.48
  text "I2C 0x76 • USB-C" at 85.4,75.4 h0.55
  text "BME280" at 88.4,28.9 h0.58
  text "QUICK CONFIGURE • SENSOR" at 66.4,27.4 h0.72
